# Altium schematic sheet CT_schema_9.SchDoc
size 147 x 119 mm
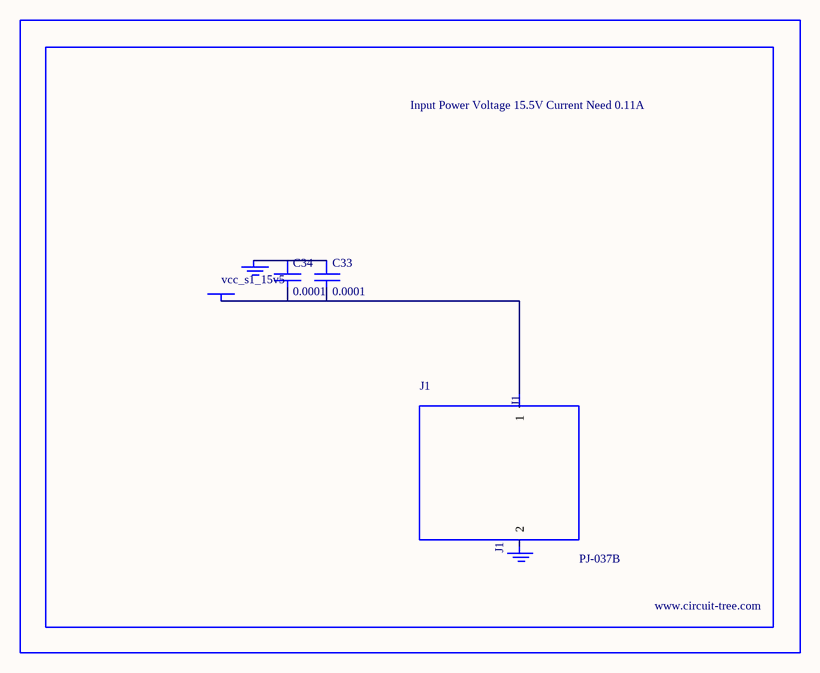
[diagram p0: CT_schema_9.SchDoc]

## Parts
BORDER8  (no value)
C33  0.0001  [EXV-9H]
C34  0.0001  [EXV-9H]
GND_INSTANCE_8_0  (no value)
GND_INSTANCE_8_1  (no value)
J1  PJ-037B  [PJ-037B_PACKAGE]
POWER_INSTANCE_8_0  vcc_s1_15v5

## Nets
NetC33_1: C33.1 C34.1 GND_INSTANCE_8_0.0(GND)
NetC33_2: C33.2 C34.2 J1.1 POWER_INSTANCE_8_0.0(PWR)

Not connected (* = marked no-connect by the designer): GND_INSTANCE_8_1 0(GND); J1 2

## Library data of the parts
BORDER8 = BORDER_PAGE8
C33 C34 = EDK107M035A9HAA
GND_INSTANCE_8_0 GND_INSTANCE_8_1 = GND
POWER_INSTANCE_8_0 = PWR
